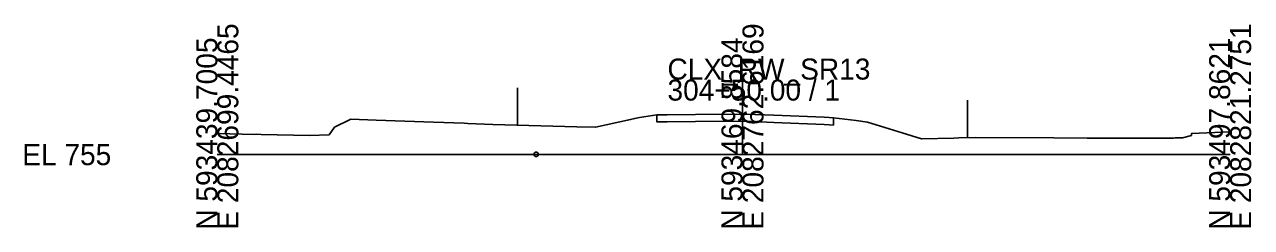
# Model space of a CAD drawing. Extents: x -26 to 2138, y -10 to 4518.
# Drawn here: x 1974.3 to 2137.8, y -9.7 to 17.3 of the extents above; entities that cross this region are included whole.
import ezdxf

# ---------------------------------------------------------------- set-up
doc = ezdxf.new("R2010")
doc.units = 0
for name, color, linetype in [('GK_Cells', 7, 'Continuous'), ('MD_X_Asphalt_Pavement', 7, 'Continuous'), ('RW_X_Esmt_SH', 7, 'Continuous'), ('UT_X_Water', 7, 'Continuous'), ('XS_X_Ground_Line', 7, 'Continuous')]:
    doc.layers.add(name, color=color, linetype=linetype)

msp = doc.modelspace()

# ---------------------------------------------------------------- linework, layer by layer
at = {"layer": 'GK_Cells'}
for p, q in [((2070, 0), (2070, 10)), ((2000, 0), (2070, 0)), ((2070, 0), (2135, 0))]:
    msp.add_line(p, q, dxfattribs=at)
at = {"layer": 'MD_X_Asphalt_Pavement'}
msp.add_lwpolyline([(2059.55, 5.31), (2058.59, 5.31), (2058.59, 4.35), (2059.55, 4.35), (2059.95, 4.36), (2063.75, 4.4), (2070.38, 4.44), (2074.17, 4.29), (2080.9, 4.03), (2081.55, 3.98), (2082.13, 3.94), (2082.13, 4.9), (2081.55, 4.94), (2080.9, 4.99), (2074.17, 5.25), (2070.38, 5.4), (2063.75, 5.35), (2059.95, 5.32), (2059.55, 5.31)], dxfattribs=at)
at = {"layer": 'RW_X_Esmt_SH'}
for p, q in [((2040, 3.92), (2040, 8.92)), ((2100, 2.25), (2100, 7.25))]:
    msp.add_line(p, q, dxfattribs=at)
at = {"layer": 'UT_X_Water'}
msp.add_circle((2042.5, 0.05), 0.3, dxfattribs=at)
at = {"layer": 'XS_X_Ground_Line'}
msp.add_lwpolyline([(2000, 2.81), (2005.01, 2.7), (2005.26, 2.71), (2005.86, 2.67), (2012.29, 2.55), (2014.91, 2.66), (2015.63, 3.68), (2017.81, 4.74), (2021.18, 4.61), (2028.83, 4.33), (2032.89, 4.18), (2032.89, 4.18), (2033.39, 4.17), (2036.73, 4.01), (2047.92, 3.69), (2050.41, 3.64), (2055.08, 4.68), (2055.64, 4.83), (2056.29, 4.95), (2058.59, 5.31), (2059.55, 5.31), (2059.95, 5.32), (2063.75, 5.35), (2070.38, 5.4), (2074.17, 5.25), (2080.9, 4.99), (2081.55, 4.94), (2082.13, 4.9), (2085.17, 4.53), (2086.66, 4.32), (2091.27, 2.9), (2093.84, 2.13), (2098.19, 2.18), (2098.83, 2.23), (2101.11, 2.27), (2111.49, 2.25), (2115.93, 2.19), (2127.46, 2.21), (2127.69, 2.22), (2127.92, 2.22), (2128.64, 2.23), (2129.84, 2.56), (2129.85, 2.84), (2135, 3.06)], dxfattribs=at)

# ---------------------------------------------------------------- texts
msp.add_text('-', height=0.0001).set_placement((2000, 0))
at = {"layer": 'GK_Cells'}
for s, p in [('E 2082699.4465', (2002.8, -10)), ('E 2082762.6169', (2072.8, -10)), ('E 2082821.2751', (2137.8, -10)), ('N 593439.7005', (2000, -10)), ('N 593469.8584', (2070, -10)), ('N 593497.8621', (2135, -10))]:
    msp.add_text(s, height=2.8, rotation=90, dxfattribs=at).set_placement(p)
for s, p in [('CLX_RW_SR13', (2060, 10)), ('304+50.00 / 1', (2060, 7.2)), ('EL 755', (1974, -1.4))]:
    msp.add_text(s, height=2.8, dxfattribs=at).set_placement(p)

doc.saveas('drawing.dxf')
